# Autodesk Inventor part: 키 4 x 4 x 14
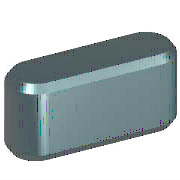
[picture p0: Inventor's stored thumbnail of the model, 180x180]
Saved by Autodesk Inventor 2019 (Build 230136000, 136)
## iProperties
Created: 2012-02
Part Number: 키 4 x 4 x 14
Material: 강철, 연강
Description: 키 및 해당 키홈
Document SubType Name: Modeling
Standard: KS B 1311
Designer: test
Standards Organization: KS
Language: ko-KR
Size Designation: 4 x 4 x 14
Categories: <MemberInstance><Categories><Category DisplayName="샤프트 부품" InternalName="7f7aeb1f-a693-4053-b835-cee3144e0d98" Mnemonic="SHFT"><Category DisplayName="키" Interna
Density: 1 g/cm^3
Appearance: 노란색
IsCustomPart: 1
Author: test
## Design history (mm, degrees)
workplane "Work Plane1"
workplane "Work Plane2"
sketch "스케치1"
  geometry: L1 (2, 2)-(12, 2); L2 (12, -2)-(2, -2); L3 (0, 9.4)-(0, -7.4) reference; L4 (-5, 0)-(30, 0) reference; L5 (14, 0)-(14, 7); A1 r 2 centre (2, 0) between (2, 2) and (2, -2); A2 r 2 centre (12, 0) between (12, -2) and (12, 2)
  constraints: 6 end point, 5 point on circle, 4 tangent, 3 point on line, 2 centre point, 1 horizontal, 1 parallel, 1 perpendicular
  dimensions: "d0" = 2 radius of A1 (= 0.5 x PB); "d13" = 2 radius of A2 (= 0.5 x PB); "d14" = 14 distance between parallel lines of L5 L3 (= NLG)
extrude "본체1" new body sketch "스케치1" taper "d3" = 0 deg; stored distance "d4" = 10
workplane "Work Plane3"
body "Solid1"
chamfer "모따기1" distance "d8" = 0.25 (= PHH); stored, may be unused: second distance "d9" = 0.25 (= PHH), angle "d15" = 45 deg
other parameters: "d1" = -2.5 (= -PNT), "d2" = 1.5 (= PH - PNT), "NLG" = 14 [user parameter; used in 3 equation terms], "PB" = 4 [user parameter; used in 2 equation terms], "PNT" = 2.5 [user parameter; used in 2 equation terms], "PH" = 4 [user parameter; used in 1 equation term], "PHH" = 0.25 [user parameter; used in 2 equation terms], "d10" = 0, "d16" = 0, "d17" = 0, "d18" = 0, "PLB2" = 14 (= NLG) [user parameter], "WDMAX" = 12 [user parameter], "PLB1" = 14 (= NLG) [user parameter], "RR" = 0.08 [user parameter], "PUEB" = 1.8 [user parameter]
